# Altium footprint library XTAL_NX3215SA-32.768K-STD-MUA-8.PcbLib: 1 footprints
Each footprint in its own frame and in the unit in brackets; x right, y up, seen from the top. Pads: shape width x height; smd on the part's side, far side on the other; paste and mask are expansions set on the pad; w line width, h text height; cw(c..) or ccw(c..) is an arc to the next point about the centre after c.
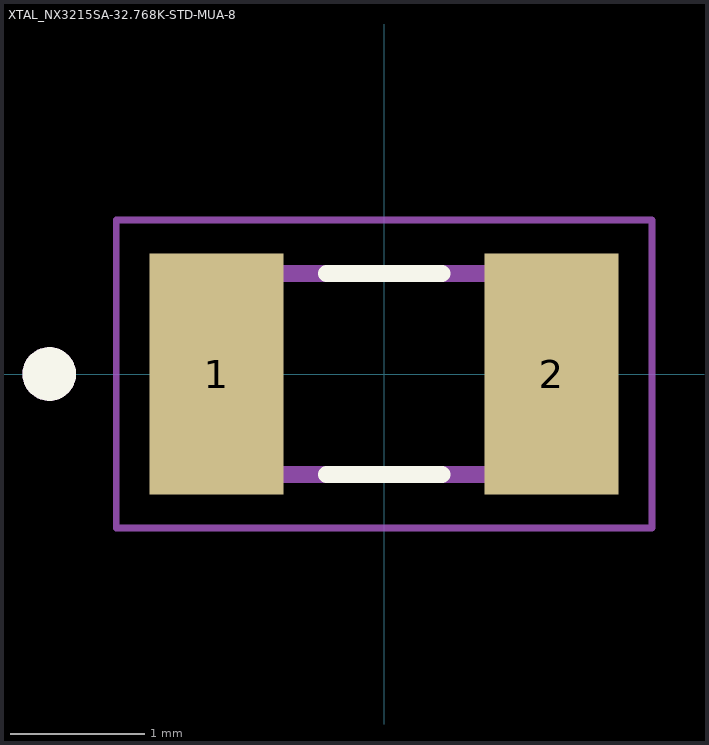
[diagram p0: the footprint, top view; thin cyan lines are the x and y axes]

## XTAL_NX3215SA-32.768K-STD-MUA-8 [mm]
pads (2):
  rect 1x1.8 smd: 1(-1.25,0) 2(1.25,0)
Top Overlay:
  circle w0.2: c-2.5,0 r0.1
  lines w0.127: -0.43,-0.75 0.43,-0.75 ; -0.43,0.75 0.43,0.75
Mechanical 13:
  circle w0.2: c-2.5,0 r0.1
  lines w0.127: -1.6,-0.75 1.6,-0.75 1.6,0.75 -1.6,0.75 -1.6,-0.75
Mechanical 15:
  lines w0.05: -2,-1.15 -2,1.15 2,1.15 2,-1.15 -2,-1.15
3D body "step_temp.STEP": height 0.9, standoff 0, extent -1.6,-0.75 1.6,0.75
